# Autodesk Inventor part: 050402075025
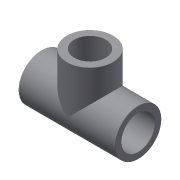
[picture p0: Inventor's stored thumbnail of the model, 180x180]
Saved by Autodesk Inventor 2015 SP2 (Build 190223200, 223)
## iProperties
Created: 2017-10
Part Number: 050402075025
Material: Generic
Description: PLASSON TEE THR-CEM PVC 75-2.1/2"
Document SubType Name: Modeling
Designer: KIM
Density: 1 g/cm^3
Appearance: Default
Author: KIM
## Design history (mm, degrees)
derived "050402.ipt"
feature "Solid1::050402.ipt"
feature "Solid2::050402.ipt"
tag "TaggingFeature1"
body "Solid1"
other parameters: "d2" = 44, "d4" = 75, "d5" = 65.0034, "d7" = 0.72226, "d8" = 44, "d9" = 85, "d15" = 0, "d18" = 72.226, "d24" = 0.72226, "d30" = 72.226, "d31" = 29, "d32" = 0, "d33" = 65.0034, "d35" = 0, "G_" = 72.226, "lt_" = 29, "l_" = 44, "h_" = 85, "d_" = 75
